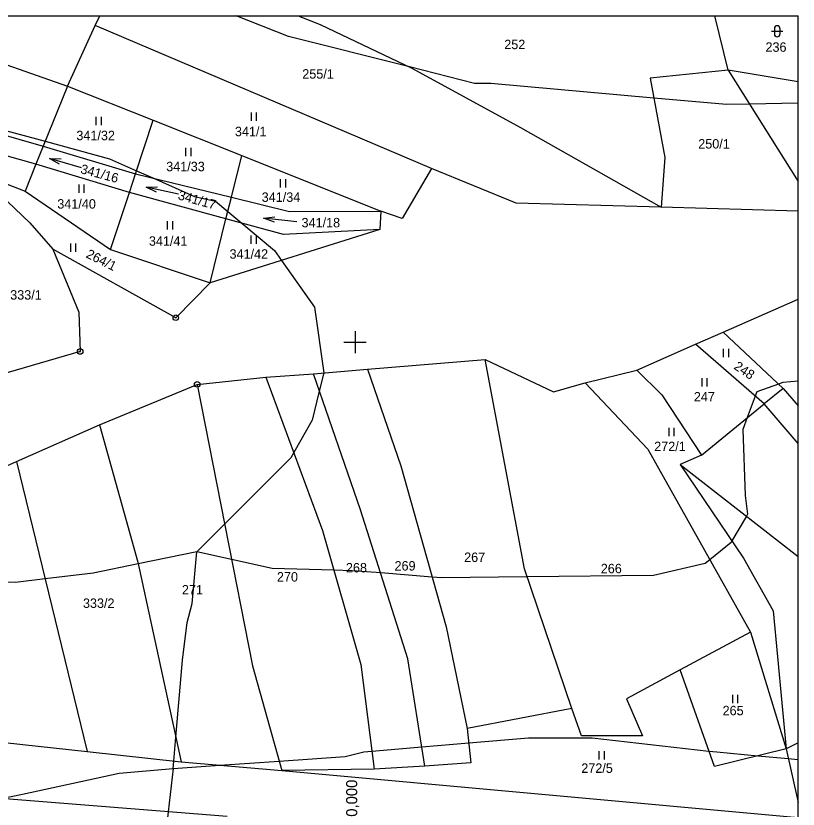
# Model space of a CAD drawing. Extents: x -756640 to -756220, y -1116031 to -1115741.
# Drawn here: x -756361.1 to -756220.1, y -1115884.2 to -1115741.2 of the extents above; entities that cross this region are included whole.
import ezdxf

# ---------------------------------------------------------------- set-up
doc = ezdxf.new("R2010")
doc.units = 0
for name, color, linetype in [('BPEJ', 7, 'Continuous'), ('Katastr_HRANICE DRÁHY', 7, 'Continuous'), ('Katastr_Hranice parcel', 7, 'Continuous'), ('Katastr_Parcelní čísla', 7, 'Continuous'), ('Katastr_Značky kultur', 7, 'Continuous'), ('čtvercová síť', 7, 'Continuous')]:
    doc.layers.add(name, color=color, linetype=linetype)

# ---------------------------------------------------------------- blocks, each defined once
blk = doc.blocks.new('C691')
at = {"layer": 'čtvercová síť'}
for p, q in [((0, 0.5), (0, -0.5)), ((-0.5, 0), (0.5, 0))]:
    blk.add_line(p, q, dxfattribs=at)

msp = doc.modelspace()

# ---------------------------------------------------------------- linework, layer by layer
at = {"layer": 'BPEJ'}
for points in [[(-756220.13, -1115756.94), (-756228.88, -1115757.1), (-756233.07, -1115757.17), (-756246.16, -1115756), (-756275.51, -1115753.36), (-756278.48, -1115753.36), (-756290.19, -1115750.39), (-756312, -1115744.87), (-756321.46, -1115741.18)], [(-756364.61, -1115761.42), (-756355.88, -1115763.78), (-756344.25, -1115766.93), (-756339.39, -1115769.09), (-756336.47, -1115770.39), (-756328.97, -1115773.72), (-756325.15, -1115774.57), (-756322.94, -1115776.43), (-756320.41, -1115778.55), (-756314.54, -1115783.48), (-756313.28, -1115785.26), (-756307.33, -1115793.67), (-756305.63, -1115805.55), (-756306.45, -1115808.81), (-756307.75, -1115814.03), (-756311.06, -1115819.9), (-756311.57, -1115820.82), (-756321.76, -1115831.01), (-756323.53, -1115832.78), (-756328.55, -1115837.79)], [(-756220.13, -1115807.05), (-756222.89, -1115807.24), (-756223.7, -1115807.54), (-756227.56, -1115808.94)], [(-756227.56, -1115808.94), (-756227.86, -1115809.73), (-756229.3, -1115813.58), (-756230.1, -1115815.73), (-756229.68, -1115827.61), (-756229.26, -1115831.01), (-756229.45, -1115831.34), (-756232.07, -1115835.82), (-756232.23, -1115836.1), (-756236.03, -1115839.21), (-756236.89, -1115839.92), (-756246.23, -1115842.04), (-756268.99, -1115842.29), (-756284.42, -1115842.46), (-756286.13, -1115842.33), (-756295.38, -1115841.6), (-756300.54, -1115841.19), (-756303.81, -1115841.09), (-756314.97, -1115840.77), (-756322.27, -1115839.17), (-756328.55, -1115837.79)], [(-756328.55, -1115837.79), (-756339.1, -1115839.95), (-756347.22, -1115841.61), (-756355.89, -1115842.66)], [(-756332.79, -1115876.83), (-756332.67, -1115875.5), (-756332.3, -1115871.2), (-756331.09, -1115857.31), (-756330.24, -1115850.52), (-756329.39, -1115847.13), (-756328.55, -1115837.79)], [(-756355.89, -1115842.66), (-756361.22, -1115843.31), (-756373.35, -1115843.11), (-756382.69, -1115842.96), (-756387.1, -1115842.89), (-756391.28, -1115843.07), (-756402.93, -1115843.59), (-756415.53, -1115844.16), (-756432.93, -1115845.86), (-756441.01, -1115847.26), (-756445.2, -1115847.98), (-756454.99, -1115849.67), (-756461.04, -1115851.77), (-756475.79, -1115856.89), (-756487.39, -1115864.74), (-756490.21, -1115866.65)], [(-756332.79, -1115876.83), (-756324.36, -1115876.25), (-756313.7, -1115875.52), (-756301.81, -1115874.71), (-756298.42, -1115873.86), (-756296.98, -1115873.74), (-756287.94, -1115872.96), (-756279.52, -1115872.24), (-756268.72, -1115871.32), (-756257.26, -1115871.32), (-756236.21, -1115873.7), (-756234.77, -1115873.86), (-756227.37, -1115874.56), (-756221.9, -1115875.07), (-756220.13, -1115875.24)], [(-756381.59, -1115885.74), (-756363.76, -1115882.25), (-756359.95, -1115881.5), (-756342.55, -1115877.68), (-756332.79, -1115876.83)], [(-756332.79, -1115876.83), (-756333.68, -1115884.64), (-756334.91, -1115895.5), (-756336.18, -1115900.59), (-756336.18, -1115903.45), (-756336.18, -1115910.78), (-756335.33, -1115912.48), (-756335.76, -1115917.57), (-756331.52, -1115931.14), (-756325.58, -1115939.63), (-756314.15, -1115948.84), (-756302.4, -1115958.32), (-756299.27, -1115960.85)]]:
    msp.add_lwpolyline(points, dxfattribs=at)
at = {"layer": 'Defpoints'}
for p in [(-756640.13, -1115741.18), (-756220.13, -1116030.18)]:
    msp.add_line(p, (-756220.13, -1115741.18), dxfattribs=at)
at = {"layer": 'Katastr_HRANICE DRÁHY'}
for points in [[(-756286.21, -1115768.68), (-756291.51, -1115777.69)], [(-756270.95, -1115774.94), (-756286.21, -1115768.68)], [(-756244.82, -1115775.67), (-756270.95, -1115774.94)], [(-756295.36, -1115776.36), (-756295.53, -1115779.71)], [(-756291.51, -1115777.69), (-756295.36, -1115776.36)], [(-756220.13, -1115776.36), (-756244.82, -1115775.67)], [(-756295.53, -1115779.71), (-756326.15, -1115789.29)], [(-756332.32, -1115795.59), (-756354.5, -1115783.25)], [(-756354.5, -1115783.25), (-756349.78, -1115794.61)], [(-756326.15, -1115789.29), (-756332.32, -1115795.59)], [(-756233.67, -1115798.18), (-756220.13, -1115792.24)], [(-756349.78, -1115794.61), (-756349.55, -1115801.67)], [(-756238.65, -1115800.38), (-756233.67, -1115798.18)], [(-756249.19, -1115805.03), (-756238.65, -1115800.38)], [(-756349.55, -1115801.67), (-756364.06, -1115805.89)], [(-756297.75, -1115804.84), (-756276.55, -1115803.13)], [(-756276.55, -1115803.13), (-756264.22, -1115808.93)], [(-756307.52, -1115805.72), (-756297.75, -1115804.84)], [(-756258.54, -1115807.32), (-756249.19, -1115805.03)], [(-756328.46, -1115807.61), (-756316.08, -1115806.33)], [(-756316.08, -1115806.33), (-756307.52, -1115805.72)], [(-756346.1, -1115814.88), (-756328.46, -1115807.61)], [(-756264.22, -1115808.93), (-756258.54, -1115807.32)], [(-756361.05, -1115821.51), (-756346.1, -1115814.88)], [(-756376.92, -1115828.62), (-756361.05, -1115821.51)]]:
    msp.add_lwpolyline(points, dxfattribs=at)
at = {"layer": 'Katastr_Hranice parcel'}
for points in [[(-756346.83, -1115742.94), (-756346.01, -1115741.18)], [(-756310.26, -1115741.18), (-756306.31, -1115742.72)], [(-756232.74, -1115750.96), (-756235.15, -1115741.18)], [(-756351.86, -1115753.85), (-756346.83, -1115742.94)], [(-756286.21, -1115768.68), (-756346.83, -1115742.94)], [(-756306.31, -1115742.72), (-756289.79, -1115750.58)], [(-756370.72, -1115747.22), (-756351.86, -1115753.85)], [(-756289.79, -1115750.58), (-756270.17, -1115761.29)], [(-756232.74, -1115750.96), (-756246.82, -1115752.43)], [(-756220.13, -1115753.07), (-756232.74, -1115750.96)], [(-756232.74, -1115750.96), (-756220.13, -1115771.02)], [(-756246.82, -1115752.43), (-756244.17, -1115766.71)], [(-756351.86, -1115753.85), (-756356.23, -1115764.66)], [(-756351.86, -1115753.85), (-756336.39, -1115760)], [(-756382.59, -1115757.09), (-756356.23, -1115764.66)], [(-756357.53, -1115767.92), (-756383.55, -1115760.55)], [(-756339.57, -1115769.63), (-756336.39, -1115760)], [(-756336.39, -1115760), (-756320.43, -1115766.37)], [(-756270.17, -1115761.29), (-756244.82, -1115775.67)], [(-756356.23, -1115764.66), (-756357.53, -1115767.92)], [(-756356.23, -1115764.66), (-756339.57, -1115769.63)], [(-756322.3, -1115773.86), (-756320.43, -1115766.37)], [(-756320.43, -1115766.37), (-756295.36, -1115776.36)], [(-756357.53, -1115767.92), (-756359.47, -1115772.77)], [(-756340.69, -1115773.02), (-756357.53, -1115767.92)], [(-756244.17, -1115766.71), (-756244.82, -1115775.67)], [(-756368.19, -1115769.4), (-756358.61, -1115778.51)], [(-756368.19, -1115769.4), (-756359.47, -1115772.77)], [(-756340.69, -1115773.02), (-756339.57, -1115769.63)], [(-756339.57, -1115769.63), (-756322.3, -1115773.86)], [(-756359.47, -1115772.77), (-756344.08, -1115783.27)], [(-756344.08, -1115783.27), (-756340.69, -1115773.02)], [(-756323.28, -1115777.77), (-756340.69, -1115773.02)], [(-756323.28, -1115777.77), (-756322.3, -1115773.86)], [(-756322.3, -1115773.86), (-756311.8, -1115776.44)], [(-756311.8, -1115776.44), (-756295.36, -1115776.36)], [(-756326.15, -1115789.29), (-756323.28, -1115777.77)], [(-756312.92, -1115780.6), (-756323.28, -1115777.77)], [(-756358.61, -1115778.51), (-756354.5, -1115783.25)], [(-756295.53, -1115779.71), (-756312.92, -1115780.6)], [(-756344.08, -1115783.27), (-756326.15, -1115789.29)], [(-756233.67, -1115798.18), (-756222.85, -1115808.34)], [(-756226.28, -1115811.1), (-756238.65, -1115800.38)], [(-756269.47, -1115840.87), (-756276.55, -1115803.13)], [(-756297.75, -1115804.84), (-756291.76, -1115822.27)], [(-756249.19, -1115805.03), (-756244.72, -1115809.5)], [(-756316.08, -1115806.33), (-756305.85, -1115833.96)], [(-756299.01, -1115830.2), (-756307.52, -1115805.72)], [(-756328.46, -1115807.61), (-756318.52, -1115858.32)], [(-756258.54, -1115807.32), (-756247.22, -1115819.31)], [(-756244.72, -1115809.5), (-756237.54, -1115820.36)], [(-756222.85, -1115808.34), (-756226.28, -1115811.1)], [(-756222.85, -1115808.34), (-756220.13, -1115811.48)], [(-756237.54, -1115820.36), (-756226.28, -1115811.1)], [(-756220.13, -1115818.25), (-756226.28, -1115811.1)], [(-756346.1, -1115814.88), (-756339.17, -1115839.64)], [(-756247.22, -1115819.31), (-756228.69, -1115852.25)], [(-756237.54, -1115820.36), (-756241.38, -1115822.04)], [(-756361.05, -1115821.51), (-756348.29, -1115873.78)], [(-756291.76, -1115822.27), (-756283.6, -1115851.33)], [(-756241.38, -1115822.04), (-756229.98, -1115838.91)], [(-756241.38, -1115822.04), (-756220.13, -1115838.61)], [(-756290.46, -1115857.06), (-756299.01, -1115830.2)], [(-756305.85, -1115833.96), (-756298.96, -1115858.11)], [(-756229.98, -1115838.91), (-756224.63, -1115848.41)], [(-756339.17, -1115839.64), (-756331.33, -1115875.65)], [(-756260.9, -1115866), (-756269.47, -1115840.87)], [(-756224.63, -1115848.41), (-756222.3, -1115873.3)], [(-756283.6, -1115851.33), (-756279.8, -1115869.62)], [(-756228.69, -1115852.25), (-756241.41, -1115859.07)], [(-756228.69, -1115852.25), (-756222.3, -1115873.3)], [(-756298.96, -1115858.11), (-756296.57, -1115876.96)], [(-756287.4, -1115876.41), (-756290.46, -1115857.06)], [(-756318.52, -1115858.32), (-756313.23, -1115877.22)], [(-756241.41, -1115859.07), (-756251.09, -1115864.26)], [(-756235.22, -1115876.5), (-756241.41, -1115859.07)], [(-756251.09, -1115864.26), (-756248.17, -1115870.94)], [(-756260.9, -1115866), (-756279.8, -1115869.62)], [(-756259.21, -1115870.94), (-756260.9, -1115866)], [(-756279.8, -1115869.62), (-756279.14, -1115875.81)], [(-756248.17, -1115870.94), (-756259.21, -1115870.94)], [(-756363.21, -1115872.14), (-756348.29, -1115873.78)], [(-756220.13, -1115872.23), (-756222.3, -1115873.3)], [(-756348.29, -1115873.78), (-756331.33, -1115875.65)], [(-756222.3, -1115873.3), (-756235.22, -1115876.5)], [(-756222.3, -1115873.3), (-756220.13, -1115882.98)], [(-756331.33, -1115875.65), (-756313.23, -1115877.22)], [(-756287.4, -1115876.41), (-756296.57, -1115876.96)], [(-756279.14, -1115875.81), (-756287.4, -1115876.41)], [(-756323.04, -1115885.48), (-756423.52, -1115877.5)], [(-756296.57, -1115876.96), (-756313.23, -1115877.22)], [(-756313.23, -1115877.22), (-756220.13, -1115885.65)]]:
    msp.add_lwpolyline(points, dxfattribs=at)
at = {"layer": 'Katastr_Značky kultur'}
for p, q in [((-756224.41, -1115743.46), (-756224.41, -1115744.46)), ((-756223.41, -1115743.46), (-756223.41, -1115744.46)), ((-756224.91, -1115743.96), (-756222.91, -1115743.96)), ((-756346.74, -1115759.39), (-756346.74, -1115760.89)), ((-756345.74, -1115760.89), (-756345.74, -1115759.39)), ((-756318.75, -1115758.58), (-756318.75, -1115760.08)), ((-756317.75, -1115760.08), (-756317.75, -1115758.58)), ((-756330.55, -1115764.98), (-756330.55, -1115766.48)), ((-756329.55, -1115766.48), (-756329.55, -1115764.98)), ((-756349.31, -1115768.55), (-756355.07, -1115766.87)), ((-756313.5, -1115770.64), (-756313.5, -1115772.14)), ((-756312.5, -1115772.14), (-756312.5, -1115770.64)), ((-756349.82, -1115771.55), (-756349.82, -1115773.05)), ((-756348.82, -1115773.05), (-756348.82, -1115771.55)), ((-756331.81, -1115773.31), (-756337.67, -1115772.03)), ((-756310.52, -1115778.31), (-756316.48, -1115777.67)), ((-756333.86, -1115778.19), (-756333.86, -1115779.69)), ((-756332.86, -1115779.69), (-756332.86, -1115778.19)), ((-756318.77, -1115780.76), (-756318.77, -1115782.26)), ((-756317.77, -1115782.26), (-756317.77, -1115780.76)), ((-756351.31, -1115782.21), (-756351.31, -1115783.71)), ((-756350.31, -1115783.71), (-756350.31, -1115782.21)), ((-756332.37, -1115795.59), (-756332.27, -1115795.59)), ((-756349.6, -1115801.67), (-756349.5, -1115801.67)), ((-756233.65, -1115801.2), (-756233.65, -1115802.7)), ((-756232.65, -1115802.7), (-756232.65, -1115801.2)), ((-756237.51, -1115806.49), (-756237.51, -1115807.99)), ((-756236.51, -1115807.99), (-756236.51, -1115806.49)), ((-756328.51, -1115807.61), (-756328.41, -1115807.61)), ((-756243.47, -1115815.43), (-756243.47, -1115816.93)), ((-756242.47, -1115816.93), (-756242.47, -1115815.43)), ((-756231.99, -1115863.54), (-756231.99, -1115865.04)), ((-756230.99, -1115865.04), (-756230.99, -1115863.54)), ((-756256.06, -1115873.7), (-756256.06, -1115875.2)), ((-756255.06, -1115875.2), (-756255.06, -1115873.7))]:
    msp.add_line(p, q, dxfattribs=at)
for points in [[(-756353.29, -1115767.91), (-756355.07, -1115766.87), (-756353.01, -1115766.95)], [(-756335.82, -1115772.94), (-756337.67, -1115772.03), (-756335.61, -1115771.97)], [(-756314.55, -1115778.38), (-756316.48, -1115777.67), (-756314.44, -1115777.39)]]:
    msp.add_lwpolyline(points, dxfattribs=at)
for centre in [(-756332.32, -1115795.59), (-756349.55, -1115801.67), (-756328.46, -1115807.61)]:
    msp.add_circle(centre, 0.499, dxfattribs=at)
for centre, start, end in [((-756223.91, -1115743.46), 0, 180), ((-756223.91, -1115744.46), 180, 0)]:
    msp.add_arc(centre, 0.5, start, end, dxfattribs=at)

# ---------------------------------------------------------------- block references
at = {"layer": 'čtvercová síť', "xscale": 4, "yscale": 4}
msp.add_blockref('C691', (-756300, -1115800), dxfattribs=at)

# ---------------------------------------------------------------- texts
at = {"layer": 'Katastr_Parcelní čísla'}
for s, p in [('252', (-756273.11, -1115747.18)), ('236', (-756226.02, -1115747.65)), ('255/1', (-756309.52, -1115752.49)), ('341/32', (-756350.24, -1115763.59)), ('341/1', (-756321.66, -1115762.87)), ('250/1', (-756238.14, -1115765.09)), ('341/33', (-756334.05, -1115769.18)), ('341/34', (-756316.83, -1115774.7)), ('341/40', (-756353.68, -1115775.92)), ('341/18', (-756309.65, -1115779.3)), ('341/41', (-756337.17, -1115782.61)), ('341/42', (-756322.63, -1115784.95)), ('333/1', (-756362.17, -1115792.33)), ('247', (-756238.94, -1115810.69)), ('272/1', (-756246.08, -1115819.63)), ('267', (-756280.34, -1115839.62)), ('269', (-756292.89, -1115841.16)), ('268', (-756301.65, -1115841.5)), ('266', (-756255.71, -1115841.65)), ('270', (-756314.09, -1115843.15)), ('271', (-756331.22, -1115845.47)), ('333/2', (-756349.05, -1115847.9)), ('265', (-756233.75, -1115867.25)), ('272/5', (-756259.22, -1115877.63))]:
    msp.add_text(s, height=1.7, dxfattribs=at).set_placement(p)
for s, rotation, p in [('341/16', 344.9425, (-756349.63, -1115769.51)), ('341/17', 344.3999, (-756332.04, -1115774.23)), ('264/1', 333.387, (-756348.64, -1115784.66)), ('248', 326.078, (-756231.87, -1115804.72))]:
    msp.add_text(s, height=1.7, rotation=rotation, dxfattribs=at).set_placement(p)
at = {"layer": 'čtvercová síť'}
msp.add_text('Y=756300,000', height=2, rotation=90, dxfattribs=at).set_placement((-756299.61, -1115896.33))

doc.saveas('drawing.dxf')
